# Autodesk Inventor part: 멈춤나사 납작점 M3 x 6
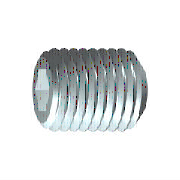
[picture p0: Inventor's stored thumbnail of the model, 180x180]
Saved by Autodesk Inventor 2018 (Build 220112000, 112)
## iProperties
IsCustomPart: 1
Created: 2012-02
Part Number: 멈춤나사 납작점 M3 x 6
Material: 강철, 연강
Description: 6각 소켓 머리 없는 멈춤 나사
Document SubType Name: Modeling
Standard: KS B 1028
Designer: mduedu
Standards Organization: KS
Language: ko-KR
Size Designation: 납작점M3x6
Categories: <MemberInstance><Categories><Category DisplayName="조임쇠" InternalName="e4da775c-781d-43d5-af7c-5136215cf5a6" Mnemonic="FSTN"><Category DisplayName="볼트" InternalN
Density: 7.85 g/cm^3
Appearance: 강철
Mass: 0.292854 g
Surface Area: 0.779766 cm^2
Volume: 0.0373062 cm^3
Author: mduedu
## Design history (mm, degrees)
sketch "스케치1"
  geometry: L1 (0, 0)-(3.5, 0); L2 (6, 0.866)-(6, 1.5); L3 (6, 1.5)-(0, 1.5); L4 (6, 0.866)-(4, 0.866); L5 (4, 0.866)-(3.5, 0); L6 (0, -0.3)-(0, 1.8) reference; L7 (0, 1.5)-(0, 0)
  constraints: 13 end point, 3 parallel, 1 collinear, 1 perpendicular, 1 point on line
  dimensions: "d0" = 2 distance of L2.start L4.end (= INTI); "d1" = 60 deg angle of L5 L1; "d2" = 3 diameter of L3 L1 (= NND); "d3" = 1.73205 diameter of L4 L1 (= 1.1547 x SW); "d5" = 6 distance from line of L2 L3.end (= NLG)
revolve "본체" sketch "스케치1" stored, may be unused: angle "d6" = 90 deg
sketch "스케치2"
  geometry: L1 (-0.433, 0.75)-(0.433, 0.75); L2 (0.433, 0.75)-(0.866, 0); L3 (0.866, 0)-(0.433, -0.75); L4 (0.433, -0.75)-(-0.433, -0.75); L5 (-0.433, -0.75)-(-0.866, 0); L6 (-0.866, 0)-(-0.433, 0.75); A1 r 0.866 centre (0, 0) between (-0.433, 0.75) and (0.433, 0.75) reference; 2 further points
  constraints: 12 end point, 2 point on circle, 1 coincident, 1 horizontal, 11 other
extrude "슬롯" join sketch "스케치2" taper "d9" = 0 deg; stored distance "d21" = 10
workaxis "Work Axis1"
workplane "Work Plane1"
body "Solid1"
chamfer "모따기1" distance "d7" = 0.30673 (= -0.5 x GD1 + 0.5 x NND); stored, may be unused: angle "d8" = 45 deg (= FAWI), second distance "d29" = 0.30673 (= -0.5 x GD1 + 0.5 x NND)
feature "스레드" dims "d11" = 6 (= NLG), "d12" = 0
chamfer "모따기2" distance "d13" = 0.30673 (= -0.5 x GD1 + 0.5 x NND); stored, may be unused: angle "d14" = 45 deg (= FAWI), second distance "d30" = 0.30673 (= -0.5 x GD1 + 0.5 x NND)
other parameters: "NND" = 3 [user parameter; used in 5 equation terms], "NLG" = 6 [user parameter; used in 2 equation terms], "INTI" = 2 [user parameter; used in 1 equation term], "FAWI" = 45 deg [user parameter; used in 2 equation terms], "SW" = 1.5 [user parameter; used in 2 equation terms], "GD1" = 2.38655 (= THREADDIA - 1.2269 x PTC) [user parameter; used in 4 equation terms], "d4" = 0, "FAWI1" = 45 deg [user parameter], "d15" = 0, "d31" = 0, "GUL" = 0.30673 (= 0.61345 x PTC) [user parameter], "SPD" = 2 [user parameter], "TOA" = 30 deg [user parameter], "THREADDIA" = 3 [user parameter; used in 1 equation term], "PTC" = 0.5 [user parameter; used in 4 equation terms], "GAL" = 0.30673 (= 0.61345 x PTC) [user parameter], "E0" = 1.7325 (= 1.155 x SW) [user parameter]
